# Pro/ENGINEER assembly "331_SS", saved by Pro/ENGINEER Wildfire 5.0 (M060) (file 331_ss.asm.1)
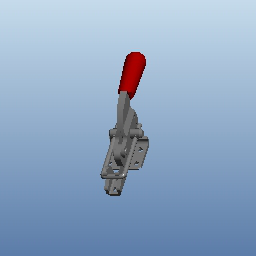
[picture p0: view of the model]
Units: PSOLunit; MM, KILOGRAM, SECS

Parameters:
  NN = "331-SS Series"
  NT = "Stainless Steel Clamps - Latch Clamps"
  NB = "331-SS"
  NBSYN = "$MN."
  LINA = "331-SS"
  MN = "331-SS"
  EDP = "53319"
  W = "0.25kg [0.56lb]"
  T = "M5x0.8"
  SUPPLIER = "DESTACO"
  ARTICLENO = "331-SS"
  BOMINFO = "331-SS"
  CREATOR = "CADENAS GmbH"

Other parameters: HC, DM, OHL, A, AIN, B, BIN, C, CIN, D, DIN, E, EIN, F, FIN, GIN, H, HIN, J, JIN, J1, J1IN, K, KIN, L, LIN, N, NIN, O, OIN, QMIN, QMININ, QMAX, QMAXIN

Other components: 331_SS_DUMMY_331_SS, 331903, 331908, 331907, 331911_M, 331911_M, 331911_M, 331911_M, 331906_331_RSS, 331905, 207301

Other named items: COORD, DEF-PLANE-AXIS, ASM_RIGHT, ASM_TOP, ASM_FRONT, ACS0, ACS1, ACS2, ACS3, ACS4, ACS5, ACS6, ACS7, ACS8, ACS9, ACS10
